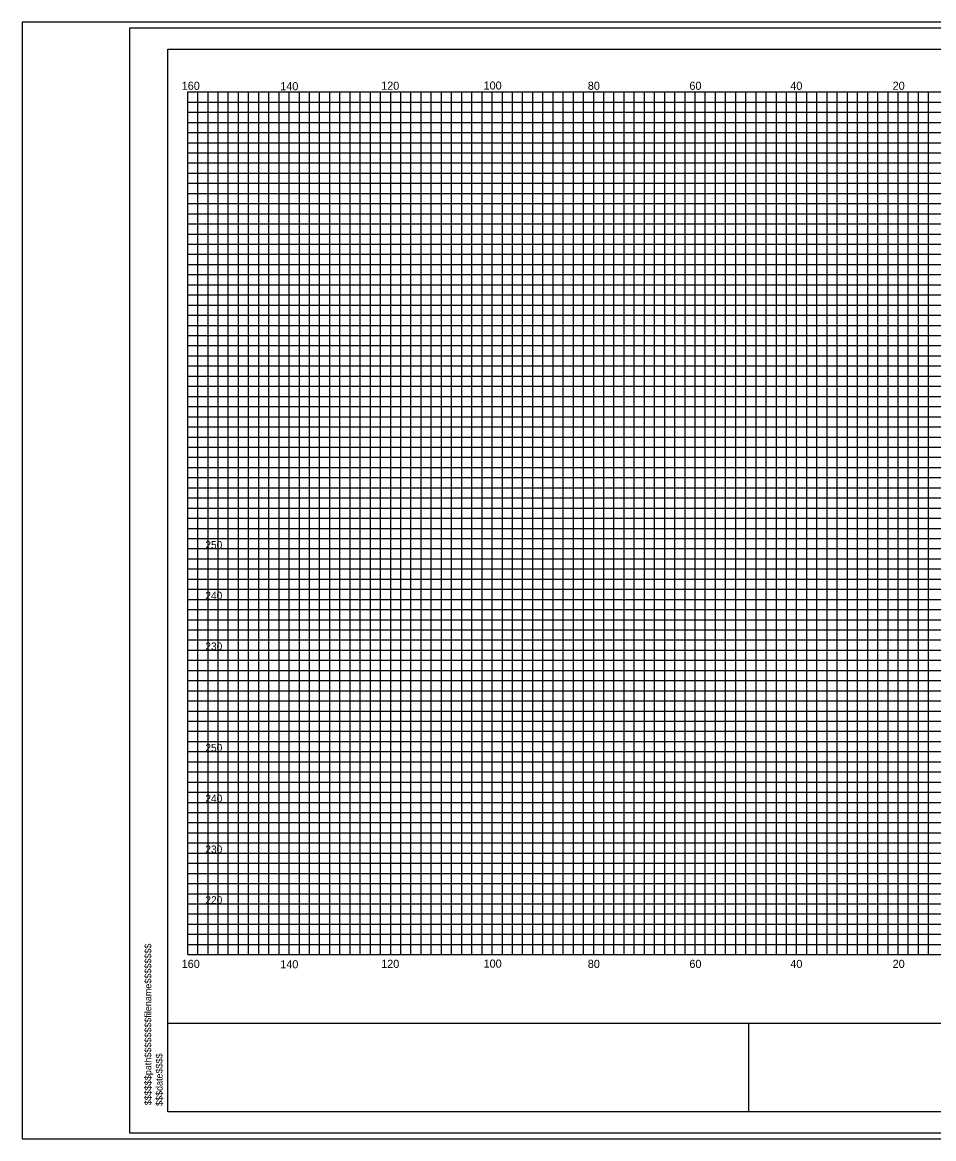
# Model space of a CAD drawing. Extents: x 967 to 1326, y 964 to 2304.
# Drawn here: x 967.4 to 1147, y 2083.7 to 2303.7 of the extents above; entities that cross this region are included whole.
import ezdxf

# ---------------------------------------------------------------- set-up
doc = ezdxf.new("R2010")
doc.units = 0
for name, color, linetype in [('Default', 7, 'Continuous'), ('RD_GPK_XS_Cell', 7, 'Continuous'), ('RD_PD_PaveShd', 7, 'Continuous'), ('RD_XS_ExGround', 7, 'Continuous'), ('RD_XS_ExPaveRet', 7, 'Continuous'), ('RD_XS_PaveOvlay', 7, 'Continuous'), ('RD_XS_TX_Elev_EX', 7, 'Continuous')]:
    doc.layers.add(name, color=color, linetype=linetype)

msp = doc.modelspace()

# ---------------------------------------------------------------- linework, layer by layer
at = {"layer": 'RD_GPK_XS_Cell'}
for p, q in [((1000, 2290), (1320, 2290)), ((1000, 2120), (1000, 2290)), ((1010, 2120), (1010, 2290)), ((1020, 2120), (1020, 2290)), ((1030, 2120), (1030, 2290)), ((1040, 2120), (1040, 2290)), ((1050, 2120), (1050, 2290)), ((1060, 2120), (1060, 2290)), ((1070, 2120), (1070, 2290)), ((1080, 2120), (1080, 2290)), ((1090, 2120), (1090, 2290)), ((1100, 2120), (1100, 2290)), ((1110, 2120), (1110, 2290)), ((1120, 2120), (1120, 2290)), ((1130, 2120), (1130, 2290)), ((1140, 2120), (1140, 2290)), ((1000, 2280), (1320, 2280)), ((1000, 2270), (1320, 2270)), ((1000, 2260), (1320, 2260)), ((1000, 2250), (1320, 2250)), ((1000, 2240), (1320, 2240)), ((1000, 2230), (1320, 2230)), ((1000, 2220), (1320, 2220)), ((1000, 2210), (1320, 2210)), ((1000, 2200), (1320, 2200)), ((1000, 2190), (1320, 2190)), ((1000, 2180), (1320, 2180)), ((1000, 2170), (1320, 2170)), ((1000, 2160), (1320, 2160)), ((1000, 2150), (1320, 2150)), ((1000, 2140), (1320, 2140)), ((1000, 2130), (1320, 2130)), ((1000, 2120), (1320, 2120))]:
    msp.add_line(p, q, dxfattribs=at)
at = {"layer": 'RD_PD_PaveShd'}
for p, q in [((996.11, 2088.98), (996.11, 2298.46)), ((996.11, 2298.46), (1323.89, 2298.46)), ((996.11, 2106.49), (1323.89, 2106.49)), ((1110.59, 2088.98), (1110.59, 2106.56)), ((1323.89, 2088.98), (996.11, 2088.98))]:
    msp.add_line(p, q, dxfattribs=at)
at = {"layer": 'RD_XS_ExGround'}
for p, q in [((1000, 2288), (1320, 2288)), ((1002, 2120), (1002, 2290)), ((1004, 2120), (1004, 2290)), ((1006, 2120), (1006, 2290)), ((1008, 2120), (1008, 2290)), ((1012, 2120), (1012, 2290)), ((1014, 2120), (1014, 2290)), ((1016, 2120), (1016, 2290)), ((1018, 2120), (1018, 2290)), ((1022, 2120), (1022, 2290)), ((1024, 2120), (1024, 2290)), ((1026, 2120), (1026, 2290)), ((1028, 2120), (1028, 2290)), ((1032, 2120), (1032, 2290)), ((1034, 2120), (1034, 2290)), ((1036, 2120), (1036, 2290)), ((1038, 2120), (1038, 2290)), ((1042, 2120), (1042, 2290)), ((1044, 2120), (1044, 2290)), ((1046, 2120), (1046, 2290)), ((1048, 2120), (1048, 2290)), ((1052, 2120), (1052, 2290)), ((1054, 2120), (1054, 2290)), ((1056, 2120), (1056, 2290)), ((1058, 2120), (1058, 2290)), ((1062, 2120), (1062, 2290)), ((1064, 2120), (1064, 2290)), ((1066, 2120), (1066, 2290)), ((1068, 2120), (1068, 2290)), ((1072, 2120), (1072, 2290)), ((1074, 2120), (1074, 2290)), ((1076, 2120), (1076, 2290)), ((1078, 2120), (1078, 2290)), ((1082, 2120), (1082, 2290)), ((1084, 2120), (1084, 2290)), ((1086, 2120), (1086, 2290)), ((1088, 2120), (1088, 2290)), ((1092, 2120), (1092, 2290)), ((1094, 2120), (1094, 2290)), ((1096, 2120), (1096, 2290)), ((1098, 2120), (1098, 2290)), ((1102, 2120), (1102, 2290)), ((1104, 2120), (1104, 2290)), ((1106, 2120), (1106, 2290)), ((1108, 2120), (1108, 2290)), ((1112, 2120), (1112, 2290)), ((1114, 2120), (1114, 2290)), ((1116, 2120), (1116, 2290)), ((1118, 2120), (1118, 2290)), ((1122, 2120), (1122, 2290)), ((1124, 2120), (1124, 2290)), ((1126, 2120), (1126, 2290)), ((1128, 2120), (1128, 2290)), ((1132, 2120), (1132, 2290)), ((1134, 2120), (1134, 2290)), ((1136, 2120), (1136, 2290)), ((1138, 2120), (1138, 2290)), ((1142, 2120), (1142, 2290)), ((1144, 2120), (1144, 2290)), ((1146, 2120), (1146, 2290)), ((1000, 2286), (1320, 2286)), ((1000, 2284), (1320, 2284)), ((1000, 2282), (1320, 2282)), ((1000, 2278), (1320, 2278)), ((1000, 2276), (1320, 2276)), ((1000, 2274), (1320, 2274)), ((1000, 2272), (1320, 2272)), ((1000, 2268), (1320, 2268)), ((1000, 2266), (1320, 2266)), ((1000, 2264), (1320, 2264)), ((1000, 2262), (1320, 2262)), ((1000, 2258), (1320, 2258)), ((1000, 2256), (1320, 2256)), ((1000, 2254), (1320, 2254)), ((1000, 2252), (1320, 2252)), ((1000, 2248), (1320, 2248)), ((1000, 2246), (1320, 2246)), ((1000, 2244), (1320, 2244)), ((1000, 2242), (1320, 2242)), ((1000, 2238), (1320, 2238)), ((1000, 2236), (1320, 2236)), ((1000, 2234), (1320, 2234)), ((1000, 2232), (1320, 2232)), ((1000, 2228), (1320, 2228)), ((1000, 2226), (1320, 2226)), ((1000, 2224), (1320, 2224)), ((1000, 2222), (1320, 2222)), ((1000, 2218), (1320, 2218)), ((1000, 2216), (1320, 2216)), ((1000, 2214), (1320, 2214)), ((1000, 2212), (1320, 2212)), ((1000, 2208), (1320, 2208)), ((1000, 2206), (1320, 2206)), ((1000, 2204), (1320, 2204)), ((1000, 2202), (1320, 2202)), ((1000, 2198), (1320, 2198)), ((1000, 2196), (1320, 2196)), ((1000, 2194), (1320, 2194)), ((1000, 2192), (1320, 2192)), ((1000, 2188), (1320, 2188)), ((1000, 2186), (1320, 2186)), ((1000, 2184), (1320, 2184)), ((1000, 2182), (1320, 2182)), ((1000, 2178), (1320, 2178)), ((1000, 2176), (1320, 2176)), ((1000, 2174), (1320, 2174)), ((1000, 2172), (1320, 2172)), ((1000, 2168), (1320, 2168)), ((1000, 2166), (1320, 2166)), ((1000, 2164), (1320, 2164)), ((1000, 2162), (1320, 2162)), ((1000, 2158), (1320, 2158)), ((1000, 2156), (1320, 2156)), ((1000, 2154), (1320, 2154)), ((1000, 2152), (1320, 2152)), ((1000, 2148), (1320, 2148)), ((1000, 2146), (1320, 2146)), ((1000, 2144), (1320, 2144)), ((1000, 2142), (1320, 2142)), ((1000, 2138), (1320, 2138)), ((1000, 2136), (1320, 2136)), ((1000, 2134), (1320, 2134)), ((1000, 2132), (1320, 2132)), ((1000, 2128), (1320, 2128)), ((1000, 2126), (1320, 2126)), ((1000, 2124), (1320, 2124)), ((1000, 2122), (1320, 2122))]:
    msp.add_line(p, q, dxfattribs=at)
at = {"layer": 'RD_XS_PaveOvlay'}
msp.add_lwpolyline([(967.41, 2083.72), (1326.28, 2083.72), (1326.28, 2303.72), (967.41, 2303.72)], close=True, dxfattribs=at)
at = {"layer": 'RD_XS_TX_Elev_EX'}
for points in [[(967.41, 2083.72), (1326.28, 2083.72), (1326.28, 2303.72), (967.41, 2303.72)], [(988.52, 2084.84), (1326.28, 2084.84), (1326.28, 2302.6), (988.52, 2302.6)]]:
    msp.add_lwpolyline(points, close=True, dxfattribs=at)

# ---------------------------------------------------------------- texts
at = {"layer": 'Default'}
for s, p in [('250', (1003.47, 2200)), ('240', (1003.47, 2190)), ('230', (1003.47, 2180)), ('250', (1003.47, 2160)), ('240', (1003.47, 2150)), ('230', (1003.47, 2140)), ('220', (1003.47, 2130))]:
    msp.add_text(s, height=1.5, dxfattribs=at).set_placement(p)
for s, p in [('$$$$$$path$$$$$$$$filename$$$$$$$$', (992.83, 2090.31)), ('$$$date$$$$', (995.04, 2090.17))]:
    msp.add_text(s, height=1.3258, rotation=90, dxfattribs=at).set_placement(p)
at = {"layer": 'RD_XS_ExPaveRet'}
for s, p in [('160', (998.81, 2290.42)), ('140', (1018.23, 2290.34)), ('120', (1038.12, 2290.43)), ('100', (1058.3, 2290.47)), ('80', (1078.84, 2290.42)), ('60', (1098.86, 2290.42)), ('40', (1118.75, 2290.41)), ('20', (1138.91, 2290.42)), ('160', (998.81, 2117.37)), ('140', (1018.23, 2117.29)), ('120', (1038.12, 2117.38)), ('100', (1058.3, 2117.42)), ('80', (1078.84, 2117.37)), ('60', (1098.86, 2117.37)), ('40', (1118.75, 2117.36)), ('20', (1138.91, 2117.37))]:
    msp.add_text(s, height=1.6, dxfattribs=at).set_placement(p)

doc.saveas('drawing.dxf')
